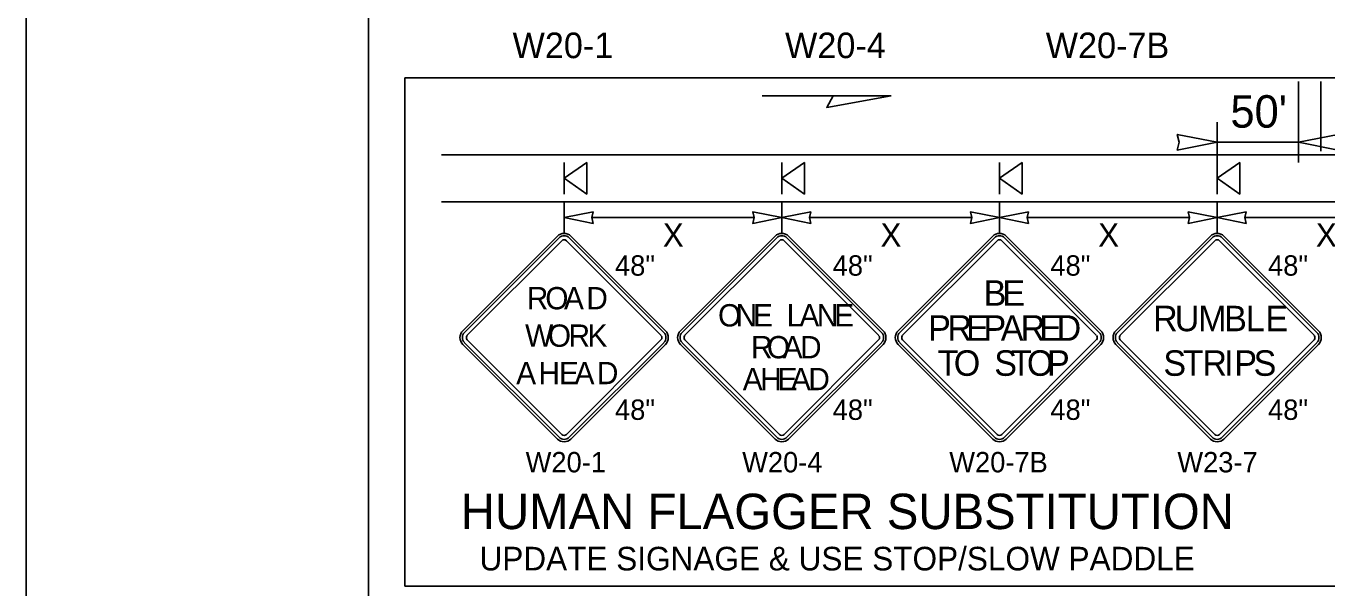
# Model space of a CAD drawing. Extents: x 99999.1 to 100095.7, y 99995 to 100010.7.
# Drawn here: x 100039.062 to 100042.622, y 100003.222 to 100004.76 of the extents above; entities that cross this region are included whole.
import ezdxf

# ---------------------------------------------------------------- set-up
doc = ezdxf.new("R2010")
doc.units = 0
for name, color, linetype in [('RD_ED_ShoulderPavedEdge', 7, 'Continuous'), ('RD_MK_LineEdgeWhite', 7, 'Continuous'), ('SH_DE_DetailHeading2Text', 7, 'Continuous'), ('SH_GI_PlotLimits', 7, 'Continuous'), ('SH_GI_SheetBorder', 7, 'Continuous'), ('TR_SN_ConstructionSigns', 7, 'Continuous'), ('TR_WZ_PortableSignMountBlk-Org', 7, 'Continuous'), ('TR_WZ_WorkZoneDetails', 7, 'Continuous'), ('TR_WZ_WorkZoneTextCurrent', 7, 'Continuous')]:
    doc.layers.add(name, color=color, linetype=linetype)

msp = doc.modelspace()

# ---------------------------------------------------------------- linework, layer by layer
at = {"layer": 'RD_ED_ShoulderPavedEdge'}
msp.add_line((100040.2, 100004.2788), (100043.6825, 100004.2788), dxfattribs=at)
at = {"layer": 'RD_MK_LineEdgeWhite'}
msp.add_line((100040.2, 100004.4079), (100043.6825, 100004.4079), dxfattribs=at)
at = {"layer": 'SH_GI_PlotLimits'}
msp.add_lwpolyline([(100039.0625, 99999.6875), (100056.0625, 99999.6875), (100056.0625, 100010.6875), (100039.0625, 100010.6875)], close=True, dxfattribs=at)
at = {"layer": 'SH_GI_SheetBorder'}
msp.add_line((100040, 100010.375), (100040, 100000), dxfattribs=at)
at = {"layer": 'TR_SN_ConstructionSigns'}
for p, q in [((100040.5172, 100004.185), (100040.2583, 100003.926)), ((100040.5219, 100004.1804), (100040.2629, 100003.9214)), ((100040.2706, 100003.9137), (100040.5296, 100004.1726)), ((100040.5419, 100004.1726), (100040.8009, 100003.9137)), ((100040.8086, 100003.9214), (100040.5496, 100004.1804)), ((100040.8132, 100003.926), (100040.5542, 100004.185)), ((100041.1132, 100004.185), (100040.8542, 100003.926)), ((100041.1178, 100004.1804), (100040.8588, 100003.9214)), ((100040.8665, 100003.9137), (100041.1255, 100004.1726)), ((100041.1378, 100004.1726), (100041.3968, 100003.9137)), ((100041.4045, 100003.9214), (100041.1455, 100004.1804)), ((100041.4091, 100003.926), (100041.1502, 100004.185)), ((100041.7091, 100004.185), (100041.4501, 100003.926)), ((100041.7137, 100004.1804), (100041.4548, 100003.9214)), ((100041.4625, 100003.9137), (100041.7214, 100004.1726)), ((100041.7338, 100004.1726), (100041.9927, 100003.9137)), ((100042.0004, 100003.9214), (100041.7415, 100004.1804)), ((100042.0051, 100003.926), (100041.7461, 100004.185)), ((100042.305, 100004.185), (100042.0461, 100003.926)), ((100042.3097, 100004.1804), (100042.0507, 100003.9214)), ((100042.0584, 100003.9137), (100042.3174, 100004.1726)), ((100042.3297, 100004.1726), (100042.5887, 100003.9137)), ((100042.5964, 100003.9214), (100042.3374, 100004.1804)), ((100042.601, 100003.926), (100042.342, 100004.185)), ((100040.2583, 100003.889), (100040.5172, 100003.63)), ((100040.2629, 100003.8936), (100040.5219, 100003.6347)), ((100040.5296, 100003.6424), (100040.2706, 100003.9013)), ((100040.8009, 100003.9013), (100040.5419, 100003.6424)), ((100040.5496, 100003.6347), (100040.8086, 100003.8936)), ((100040.5542, 100003.63), (100040.8132, 100003.889)), ((100040.8542, 100003.889), (100041.1132, 100003.63)), ((100040.8588, 100003.8936), (100041.1178, 100003.6347)), ((100041.1255, 100003.6424), (100040.8665, 100003.9013)), ((100041.3968, 100003.9013), (100041.1378, 100003.6424)), ((100041.1455, 100003.6347), (100041.4045, 100003.8936)), ((100041.1502, 100003.63), (100041.4091, 100003.889)), ((100041.4501, 100003.889), (100041.7091, 100003.63)), ((100041.4548, 100003.8936), (100041.7137, 100003.6347)), ((100041.7214, 100003.6424), (100041.4625, 100003.9013)), ((100041.9927, 100003.9013), (100041.7338, 100003.6424)), ((100041.7415, 100003.6347), (100042.0004, 100003.8936)), ((100041.7461, 100003.63), (100042.0051, 100003.889)), ((100042.0461, 100003.889), (100042.305, 100003.63)), ((100042.0507, 100003.8936), (100042.3097, 100003.6347)), ((100042.3174, 100003.6424), (100042.0584, 100003.9013)), ((100042.5887, 100003.9013), (100042.3297, 100003.6424)), ((100042.3374, 100003.6347), (100042.5964, 100003.8936)), ((100042.342, 100003.63), (100042.601, 100003.889))]:
    msp.add_line(p, q, dxfattribs=at)
for centre, radius, start, end in [((100040.5357, 100004.1665), 0.0262, 45, 135), ((100040.5357, 100004.1665), 0.0196, 45, 135), ((100040.5357, 100004.1665), 0.00872, 45, 135), ((100041.1317, 100004.1665), 0.0262, 45, 135), ((100041.1317, 100004.1665), 0.0196, 45, 135), ((100041.1317, 100004.1665), 0.00872, 45, 135), ((100041.7276, 100004.1665), 0.0262, 45, 135), ((100041.7276, 100004.1665), 0.0196, 45, 135), ((100041.7276, 100004.1665), 0.00872, 45, 135), ((100042.3235, 100004.1665), 0.0262, 45, 135), ((100042.3235, 100004.1665), 0.0196, 45, 135), ((100042.3235, 100004.1665), 0.00872, 45, 135), ((100040.2768, 100003.9075), 0.0262, 135, 225), ((100040.2768, 100003.9075), 0.0196, 135, 225), ((100040.7947, 100003.9075), 0.0196, 315, 45), ((100040.7947, 100003.9075), 0.0262, 315, 45), ((100040.8727, 100003.9075), 0.0262, 135, 225), ((100040.8727, 100003.9075), 0.0196, 135, 225), ((100041.3906, 100003.9075), 0.0196, 315, 45), ((100041.3906, 100003.9075), 0.0262, 315, 45), ((100041.4686, 100003.9075), 0.0262, 135, 225), ((100041.4686, 100003.9075), 0.0196, 135, 225), ((100041.9866, 100003.9075), 0.0196, 315, 45), ((100041.9866, 100003.9075), 0.0262, 315, 45), ((100042.0646, 100003.9075), 0.0262, 135, 225), ((100042.0646, 100003.9075), 0.0196, 135, 225), ((100042.5825, 100003.9075), 0.0196, 315, 45), ((100042.5825, 100003.9075), 0.0262, 315, 45), ((100040.2768, 100003.9075), 0.00872, 135, 225), ((100040.7947, 100003.9075), 0.00872, 315, 45), ((100040.8727, 100003.9075), 0.00872, 135, 225), ((100041.3906, 100003.9075), 0.00872, 315, 45), ((100041.4686, 100003.9075), 0.00872, 135, 225), ((100041.9866, 100003.9075), 0.00872, 315, 45), ((100042.0646, 100003.9075), 0.00872, 135, 225), ((100042.5825, 100003.9075), 0.00872, 315, 45), ((100040.5357, 100003.6485), 0.0262, 225, 315), ((100040.5357, 100003.6485), 0.0196, 225, 315), ((100040.5357, 100003.6485), 0.00872, 225, 315), ((100041.1317, 100003.6485), 0.0262, 225, 315), ((100041.1317, 100003.6485), 0.0196, 225, 315), ((100041.1317, 100003.6485), 0.00872, 225, 315), ((100041.7276, 100003.6485), 0.0262, 225, 315), ((100041.7276, 100003.6485), 0.0196, 225, 315), ((100041.7276, 100003.6485), 0.00872, 225, 315), ((100042.3235, 100003.6485), 0.0262, 225, 315), ((100042.3235, 100003.6485), 0.0196, 225, 315), ((100042.3235, 100003.6485), 0.00872, 225, 315)]:
    msp.add_arc(centre, radius, start, end, dxfattribs=at)
at = {"layer": 'TR_WZ_PortableSignMountBlk-Org'}
for p, q in [((100040.5357, 100004.3003), (100040.5357, 100004.3864)), ((100041.1317, 100004.3003), (100041.1317, 100004.3864)), ((100041.7276, 100004.3003), (100041.7276, 100004.3864)), ((100042.3235, 100004.3003), (100042.3235, 100004.3864))]:
    msp.add_line(p, q, dxfattribs=at)
for points in [[(100040.5357, 100004.3433), (100040.5976, 100004.3864), (100040.5976, 100004.3003)], [(100041.1317, 100004.3433), (100041.1935, 100004.3864), (100041.1935, 100004.3003)], [(100041.7276, 100004.3433), (100041.7895, 100004.3864), (100041.7895, 100004.3003)], [(100042.3235, 100004.3433), (100042.3854, 100004.3864), (100042.3854, 100004.3003)]]:
    msp.add_lwpolyline(points, close=True, dxfattribs=at)
at = {"layer": 'TR_WZ_WorkZoneDetails'}
for p, q in [((100042.5458, 100004.4179), (100042.5458, 100004.6086)), ((100042.6076, 100004.4179), (100042.6076, 100004.6086)), ((100041.2726, 100004.5686), (100041.078, 100004.5686)), ((100042.3235, 100004.3864), (100042.3235, 100004.4974)), ((100042.5458, 100004.4974), (100042.5458, 100004.3864)), ((100042.5458, 100004.4419), (100042.3235, 100004.4419)), ((100040.5357, 100004.279), (100040.5357, 100004.1926)), ((100041.1317, 100004.279), (100041.1317, 100004.1926)), ((100041.7276, 100004.2788), (100041.7276, 100004.1926)), ((100042.3235, 100004.2788), (100042.3235, 100004.1926)), ((100041.056, 100004.2357), (100040.6114, 100004.2357)), ((100041.6519, 100004.2357), (100041.2073, 100004.2357)), ((100042.2479, 100004.2357), (100041.8033, 100004.2357)), ((100042.8438, 100004.2357), (100042.3992, 100004.2357))]:
    msp.add_line(p, q, dxfattribs=at)
for points in [[(100041.4313, 100004.5686), (100041.2546, 100004.5375), (100041.2726, 100004.5686)], [(100042.3235, 100004.4419), (100042.2143, 100004.4205), (100042.2194, 100004.4419), (100042.2143, 100004.4633)], [(100042.5458, 100004.4419), (100042.655, 100004.4205), (100042.6499, 100004.4419), (100042.655, 100004.4633)], [(100040.5357, 100004.2357), (100040.6151, 100004.2513), (100040.6114, 100004.2357), (100040.6151, 100004.2201)], [(100041.1317, 100004.2357), (100041.0523, 100004.2513), (100041.056, 100004.2357), (100041.0523, 100004.2201)], [(100041.1317, 100004.2357), (100041.211, 100004.2513), (100041.2073, 100004.2357), (100041.211, 100004.2201)], [(100041.7276, 100004.2357), (100041.6482, 100004.2513), (100041.6519, 100004.2357), (100041.6482, 100004.2201)], [(100041.7276, 100004.2357), (100041.807, 100004.2513), (100041.8033, 100004.2357), (100041.807, 100004.2201)], [(100042.3235, 100004.2357), (100042.2442, 100004.2513), (100042.2479, 100004.2357), (100042.2442, 100004.2201)], [(100042.3235, 100004.2357), (100042.4029, 100004.2513), (100042.3992, 100004.2357), (100042.4029, 100004.2201)]]:
    msp.add_lwpolyline(points, close=True, dxfattribs=at)
at = {"layer": 'TR_WZ_WorkZoneTextCurrent'}
msp.add_lwpolyline([(100040.1, 100004.6186), (100043.7858, 100004.6186), (100043.7858, 100003.2274), (100040.1, 100003.2274)], close=True, dxfattribs=at)

# ---------------------------------------------------------------- texts
at = {"layer": 'SH_DE_DetailHeading2Text'}
msp.add_text('HUMAN FLAGGER SUBSTITUTION', height=0.09689, rotation=360, dxfattribs=at).set_placement((100040.2529, 100003.3835))
at = {"layer": 'TR_SN_ConstructionSigns'}
for s, height, p in [('W20-1', 0.07, (100040.3946, 100004.6721)), ('W20-4', 0.07, (100041.1406, 100004.6721)), ('W20-7B', 0.07, (100041.8543, 100004.6721)), ('48"', 0.05581, (100040.6751, 100004.0769)), ('48"', 0.05581, (100041.271, 100004.0769)), ('48"', 0.05581, (100041.867, 100004.0769)), ('48"', 0.05581, (100042.4629, 100004.0769)), ('48"', 0.05581, (100040.6751, 100003.6823)), ('48"', 0.05581, (100041.271, 100003.6823)), ('48"', 0.05581, (100041.867, 100003.6823)), ('48"', 0.05581, (100042.4629, 100003.6823)), ('W20-1', 0.05581, (100040.4304, 100003.5387)), ('W20-4', 0.05581, (100041.0232, 100003.5387)), ('W20-7B', 0.05581, (100041.5902, 100003.5387)), ('W23-7', 0.05581, (100042.2146, 100003.5387))]:
    msp.add_text(s, height=height, rotation=360, dxfattribs=at).set_placement(p)
for s, height, p in [('B', 0.0698, (100041.6843, 100003.9947)), ('E', 0.0698, (100041.7353, 100003.9947)), ('R', 0.061, (100040.4335, 100003.9849)), ('O', 0.061, (100040.4842, 100003.9849)), ('A', 0.061, (100040.5354, 100003.9849)), ('D', 0.061, (100040.5965, 100003.9849)), ('O', 0.061, (100040.9571, 100003.938)), ('N', 0.061, (100041.0053, 100003.938)), ('E', 0.061, (100041.0529, 100003.938)), ('L', 0.061, (100041.1451, 100003.938)), ('A', 0.061, (100041.1799, 100003.938)), ('N', 0.061, (100041.2275, 100003.938)), ('E', 0.061, (100041.2751, 100003.938)), ('R', 0.0698, (100042.1481, 100003.9249)), ('U', 0.0698, (100042.2074, 100003.9249)), ('M', 0.0698, (100042.2716, 100003.9249)), ('B', 0.0698, (100042.3427, 100003.9249)), ('L', 0.0698, (100042.402, 100003.9249)), ('E', 0.0698, (100042.4557, 100003.9249)), ('P', 0.0698, (100041.5323, 100003.8988)), ('R', 0.0698, (100041.5853, 100003.8988)), ('E', 0.0698, (100041.6362, 100003.8988)), ('P', 0.0698, (100041.6837, 100003.8988)), ('A', 0.0698, (100041.7311, 100003.8988)), ('R', 0.0698, (100041.7855, 100003.8988)), ('E', 0.0698, (100041.8364, 100003.8988)), ('D', 0.0698, (100041.8839, 100003.8988)), ('W', 0.061, (100040.4289, 100003.8824)), ('O', 0.061, (100040.4912, 100003.8824)), ('R', 0.061, (100040.5479, 100003.8824)), ('K', 0.061, (100040.5998, 100003.8824)), ('R', 0.061, (100041.0474, 100003.8508)), ('O', 0.061, (100041.0908, 100003.8508)), ('A', 0.061, (100041.1341, 100003.8508)), ('D', 0.061, (100041.1817, 100003.8508)), ('T', 0.0698, (100041.5584, 100003.8029)), ('O', 0.0698, (100041.6024, 100003.8029)), ('S', 0.0698, (100041.7133, 100003.8029)), ('T', 0.0698, (100041.7586, 100003.8029)), ('O', 0.0698, (100041.8026, 100003.8029)), ('P', 0.0698, (100041.8577, 100003.8029)), ('S', 0.0698, (100042.1763, 100003.8029)), ('T', 0.0698, (100042.2294, 100003.8029)), ('R', 0.0698, (100042.2831, 100003.8029)), ('I', 0.0698, (100042.3424, 100003.8029)), ('P', 0.0698, (100042.3703, 100003.8029)), ('S', 0.0698, (100042.4233, 100003.8029)), ('A', 0.061, (100040.4045, 100003.78)), ('H', 0.061, (100040.4655, 100003.78)), ('E', 0.061, (100040.5217, 100003.78)), ('A', 0.061, (100040.5644, 100003.78)), ('D', 0.061, (100040.6255, 100003.78)), ('A', 0.061, (100041.0248, 100003.7636)), ('H', 0.061, (100041.0725, 100003.7636)), ('E', 0.061, (100041.1201, 100003.7636)), ('A', 0.061, (100041.1567, 100003.7636)), ('D', 0.061, (100041.2043, 100003.7636))]:
    msp.add_text(s, height=height, dxfattribs=at).set_placement(p)
at = {"layer": 'TR_WZ_WorkZoneTextCurrent'}
for s, height, p in [("50'", 0.08889, (100042.3599, 100004.4819)), ('X', 0.0646, (100040.8057, 100004.156)), ('X', 0.0646, (100041.4016, 100004.156)), ('X', 0.0646, (100041.9975, 100004.156)), ('X', 0.0646, (100042.5935, 100004.156)), ('UPDATE SIGNAGE & USE STOP/SLOW PADDLE', 0.064593, (100040.304, 100003.2704))]:
    msp.add_text(s, height=height, dxfattribs=at).set_placement(p)

doc.saveas('drawing.dxf')
